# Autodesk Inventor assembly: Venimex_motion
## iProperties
Shininess: 64.0
Length Units: 11269
Angle Units: 11279
Time Units: 11290
Mass Units: 11283
Length Display Precision: 3
Angle Display Precision: 2
Compacted: True
Created: 2005-01
Part Number: Venimex_motion
Document SubType Name: Assembly
Designer: David
Manufacturer: Standard
Standards Organization: Custom
Density: 0.0
Volumn: 0.0
Area: 0.0
PropertySet Name: Model Information
Control State: 0
Master: False
Checked Out: False
Author: David
